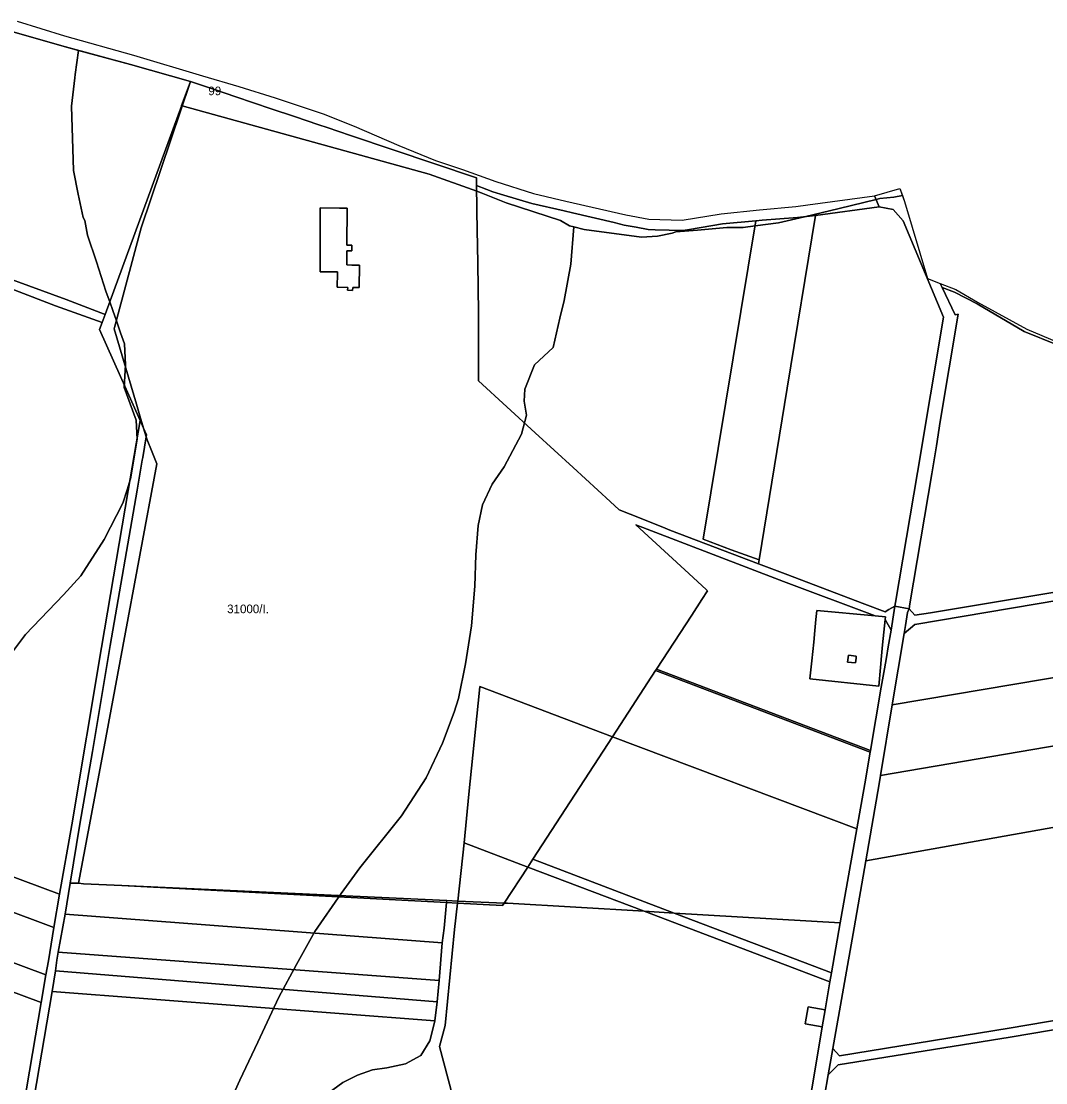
# Model space of a CAD drawing. Extents: x -541351 to -537540, y -1162694 to -1159725.
# Drawn here: x -540379 to -539786, y -1160416 to -1159801 of the extents above; entities that cross this region are included whole.
import ezdxf

# ---------------------------------------------------------------- set-up
doc = ezdxf.new("R2010")
doc.units = 0
for name, color, linetype in [('95560013', 7, 'Continuous'), ('95610013', 7, 'Continuous'), ('95640013', 7, 'Continuous'), ('95660013', 7, 'Continuous')]:
    doc.layers.add(name, color=color, linetype=linetype)

msp = doc.modelspace()

# ---------------------------------------------------------------- linework, layer by layer
at = {"layer": '95560013'}
for points in [[(-540392.94, -1159808.75), (-540387.33, -1159805.56), (-540383.07, -1159807.44), (-540355.38, -1159815.32), (-540315.69, -1159826.05), (-540281.01, -1159835.88), (-540330.36, -1159970.74), (-540352.96, -1159962.05), (-540409.96, -1159941.32), (-540413.54, -1159934.22), (-540400.75, -1159856.93)], [(-540356.83, -1160306.42), (-540508.48, -1160249.81), (-540502.49, -1160230.24), (-540493.25, -1160200.09), (-540483.27, -1160166.95), (-540480.24, -1160158.64), (-540461.87, -1160101.94), (-540442.45, -1160037.81), (-540415.15, -1159950.06), (-540408.75, -1159946.72), (-540359.07, -1159965.85), (-540332.08, -1159975.44), (-540333.53, -1159979.4), (-540310.02, -1160032.13), (-540317.01, -1160072.74), (-540332.5, -1160163.53), (-540349.68, -1160266.25)], [(-539861.7, -1160150.32), (-539749.73, -1160131.42), (-539678.3, -1160119.6), (-539674.35, -1160123.79), (-539681.25, -1160164.2), (-539874.79, -1160196.79), (-539867.81, -1160155.49)], [(-539874.79, -1160196.79), (-539681.25, -1160164.2), (-539688.29, -1160204.74), (-539881.63, -1160237.63)], [(-539695.22, -1160244.7), (-539696.27, -1160252.43), (-539890.14, -1160287.05), (-539882.34, -1160242.43), (-539881.63, -1160237.63), (-539688.29, -1160204.74)], [(-539905.29, -1160399.99), (-539909.12, -1160395.76), (-539896.76, -1160325.74), (-539890.14, -1160287.05), (-539696.27, -1160252.43), (-539714.91, -1160363.54), (-539720.67, -1160369.29), (-539807.19, -1160383.95)], [(-540514.38, -1160267.98), (-540360.1, -1160325.54), (-540363.17, -1160344.9), (-540364.58, -1160352.98), (-540522.49, -1160294.25)], [(-540522.49, -1160294.25), (-540364.58, -1160352.98), (-540367.38, -1160369.03), (-540527.1, -1160309.52)], [(-540134.18, -1160326.07), (-540135.3, -1160334.47), (-540353.51, -1160317.83), (-540350.6, -1160299.99), (-540345.66, -1160300.06), (-540342.83, -1160300.35), (-540320.73, -1160301.36), (-540132.7, -1160311.22)], [(-540132.7, -1160311.22), (-540320.73, -1160301.36), (-540132.58, -1160310.01)], [(-540527.1, -1160309.52), (-540367.38, -1160369.03), (-540379.07, -1160438.35), (-540385.21, -1160475.93), (-540388.61, -1160496.72), (-540565.8, -1160430.3), (-540549.55, -1160378.18), (-540535.84, -1160336.23)], [(-540126.4, -1160311.55), (-540132.7, -1160311.22), (-540132.58, -1160310.01), (-540126.26, -1160310.3)], [(-539919.82, -1160409.86), (-539934.65, -1160497.18), (-539939.3, -1160504.82), (-539943.59, -1160508.57), (-539953.62, -1160517.32), (-540120.93, -1160454.7), (-540124.57, -1160440.83), (-540129.29, -1160422.87), (-540136.74, -1160394.52), (-540133.58, -1160382.33), (-540128.1, -1160326.8), (-540126.4, -1160311.55), (-540100.25, -1160312.92), (-540099.35, -1160311.53), (-540097.45, -1160311.62), (-540018.39, -1160316.26), (-539910.82, -1160357.17), (-539913.57, -1160373.29), (-539923.43, -1160371.6), (-539925.11, -1160381.46), (-539915.26, -1160383.15)], [(-540126.4, -1160311.55), (-540126.26, -1160310.3), (-540099.35, -1160311.53), (-540100.25, -1160312.92)], [(-539910.82, -1160357.17), (-540018.39, -1160316.26), (-540001.04, -1160317.28), (-539909.92, -1160351.93)], [(-540353.51, -1160317.83), (-540135.3, -1160334.47), (-540137.05, -1160356.31), (-540357.49, -1160339.82)], [(-539909.92, -1160351.93), (-540001.04, -1160317.28), (-539904.97, -1160322.91)], [(-540358.21, -1160344.57), (-540357.49, -1160339.82), (-540137.05, -1160356.31), (-540138.11, -1160368.57), (-540359.02, -1160350.72)], [(-540139.42, -1160379.64), (-540361.01, -1160362.65), (-540359.02, -1160350.72), (-540138.11, -1160368.57)], [(-539622.59, -1160379.21), (-539631.8, -1160405.4), (-539638.38, -1160424.12), (-539641.15, -1160432), (-539644.34, -1160446.97), (-539647.54, -1160461.93), (-539784.61, -1160485.12), (-539921.72, -1160508.25), (-539926.62, -1160497.29), (-539911.84, -1160410.99), (-539905.99, -1160405.21), (-539806.59, -1160389.16), (-539702.88, -1160371.48), (-539612.64, -1160356.38), (-539617.44, -1160367.38)], [(-540192.75, -1160415.42), (-540201.36, -1160421.81), (-540204.8, -1160432.12), (-540205.99, -1160438.05), (-540371.68, -1160425.08), (-540361.01, -1160362.65), (-540139.42, -1160379.64), (-540139.64, -1160380.67), (-540142.35, -1160391.33), (-540147.64, -1160399.81), (-540156.43, -1160404.54), (-540167.21, -1160406.8), (-540175.62, -1160408.05), (-540184.29, -1160411.12)], [(-539913.57, -1160373.29), (-539915.26, -1160383.15), (-539925.11, -1160381.46), (-539923.43, -1160371.6)]]:
    msp.add_lwpolyline(points, close=True, dxfattribs=at)
for points in [[(-540201.36, -1160421.81), (-540192.75, -1160415.42), (-540184.29, -1160411.12), (-540175.62, -1160408.05), (-540167.21, -1160406.8), (-540156.43, -1160404.54), (-540147.64, -1160399.81), (-540142.35, -1160391.33), (-540139.64, -1160380.67), (-540139.42, -1160379.64), (-540138.11, -1160368.57), (-540137.05, -1160356.31), (-540135.3, -1160334.47), (-540134.18, -1160326.07), (-540132.7, -1160311.22), (-540126.4, -1160311.55), (-540128.1, -1160326.8), (-540133.58, -1160382.33), (-540136.74, -1160394.52), (-540129.29, -1160422.87)], [(-539702.88, -1160371.48), (-539806.59, -1160389.16), (-539905.99, -1160405.21), (-539911.84, -1160410.99), (-539909.12, -1160395.76), (-539905.29, -1160399.99), (-539807.19, -1160383.95), (-539720.67, -1160369.29)]]:
    msp.add_lwpolyline(points, dxfattribs=at)
at = {"layer": '95610013'}
msp.add_lwpolyline([(-540356.83, -1160306.42), (-540360.1, -1160325.54), (-540514.38, -1160267.98), (-540512.69, -1160262.74), (-540508.48, -1160249.81)], close=True, dxfattribs=at)
at = {"layer": '95640013'}
for points in [[(-540381.17, -1159801.03), (-540353.86, -1159809.47), (-540313.98, -1159820.68), (-540273.9, -1159832.58), (-540253.02, -1159838.81), (-540231.99, -1159845.43), (-540204.14, -1159854.61), (-540186.16, -1159861.7), (-540160.34, -1159872.99), (-540139.14, -1159881.68), (-540123.57, -1159886.83), (-540104.23, -1159893.79), (-540082.45, -1159900.78), (-540063.64, -1159905.2), (-540028.95, -1159913.17), (-540015.69, -1159915.65), (-539996.27, -1159916.14), (-539973.83, -1159912.54), (-539951.52, -1159910.12), (-539930.48, -1159908.19), (-539923.64, -1159907.28), (-539884.96, -1159902.13), (-539882.33, -1159908.49), (-539919.19, -1159913.5), (-539929.66, -1159914.61), (-539950.01, -1159916.19), (-539953.64, -1159916.52), (-539973.07, -1159918.29), (-539992.07, -1159921.5), (-539995.75, -1159922.12), (-540012.02, -1159921.72), (-540016.01, -1159921.62), (-540023.04, -1159920.31), (-540029.9, -1159919.03), (-540035.79, -1159917.63), (-540059.89, -1159911.91), (-540064.68, -1159910.77), (-540083.33, -1159906.57), (-540099.65, -1159901.66), (-540105.86, -1159899.79), (-540109.43, -1159898.41), (-540115.3, -1159896.16), (-540115.35, -1159891.67), (-540188.28, -1159867.11), (-540201.81, -1159862.55), (-540206.56, -1159860.95), (-540220.81, -1159856.16), (-540234.15, -1159851.66), (-540254.76, -1159844.72), (-540267.64, -1159840.39), (-540281.01, -1159835.88), (-540315.69, -1159826.05), (-540355.38, -1159815.32), (-540383.07, -1159807.44)], [(-539779.23, -1159988.26), (-539798.34, -1159980.7), (-539825.68, -1159964.64), (-539838.77, -1159957.82), (-539845.93, -1159955.11), (-539847.07, -1159952.76), (-539837.92, -1159956.31), (-539825.4, -1159963.61), (-539796.96, -1159979.23), (-539779.53, -1159986.52)], [(-539750.65, -1160126.47), (-539852.54, -1160143.49), (-539861.77, -1160144.89), (-539864.98, -1160141.1), (-539864.5, -1160138.25), (-539851.79, -1160063.11), (-539849.21, -1160046.91), (-539846.96, -1160032.69), (-539836.67, -1159970.59), (-539838.29, -1159970.9), (-539845.93, -1159955.11), (-539838.77, -1159957.82), (-539825.68, -1159964.64), (-539798.34, -1159980.7), (-539779.23, -1159988.26)], [(-540379.07, -1160438.35), (-540367.38, -1160369.03), (-540364.58, -1160352.98), (-540363.17, -1160344.9), (-540360.1, -1160325.54), (-540356.83, -1160306.42), (-540349.68, -1160266.25), (-540332.5, -1160163.53), (-540317.01, -1160072.74), (-540310.02, -1160032.13), (-540308.05, -1160036.54), (-540306.51, -1160041.57), (-540308.57, -1160053.59), (-540308.83, -1160055.13), (-540311.8, -1160072.45), (-540327.33, -1160162.37), (-540337.62, -1160223.7), (-540345.01, -1160265.76), (-540350.6, -1160299.99), (-540353.51, -1160317.83), (-540357.49, -1160339.82), (-540358.21, -1160344.57), (-540359.02, -1160350.72), (-540361.01, -1160362.65), (-540371.68, -1160425.08)], [(-539934.65, -1160497.18), (-539919.82, -1160409.86), (-539915.26, -1160383.15), (-539913.57, -1160373.29), (-539910.82, -1160357.17), (-539909.92, -1160351.93), (-539904.97, -1160322.91), (-539895.33, -1160268.57), (-539890.69, -1160242.45), (-539887.57, -1160224.18), (-539887.4, -1160223.2), (-539881.12, -1160186.5), (-539879.32, -1160175.96), (-539878.19, -1160169.34), (-539877.14, -1160163.23), (-539875.48, -1160153.53), (-539873.62, -1160142.07), (-539873.21, -1160139.53), (-539864.98, -1160141.1), (-539865.94, -1160143.31), (-539867.03, -1160150.82), (-539867.81, -1160155.49), (-539874.79, -1160196.79), (-539881.63, -1160237.63), (-539882.34, -1160242.43), (-539890.14, -1160287.05), (-539896.76, -1160325.74), (-539909.12, -1160395.76), (-539911.84, -1160410.99), (-539926.62, -1160497.29)]]:
    msp.add_lwpolyline(points, dxfattribs=at)
for points in [[(-540114.15, -1160009.28), (-540081.35, -1160039.35), (-540059.54, -1160059.34), (-540037.99, -1160079.08), (-540032.85, -1160083.79), (-540020.15, -1160088.95), (-540006.2, -1160094.54), (-540003.47, -1160095.63), (-539952.14, -1160115.13), (-539936.7, -1160120.97), (-539890.67, -1160138.4), (-539878.88, -1160142.86), (-539876.7, -1160141.6), (-539873.21, -1160139.53), (-539873.62, -1160142.07), (-539875.48, -1160153.53), (-539878.93, -1160147.41), (-539878.77, -1160145.8), (-539884.65, -1160145.26), (-539937.62, -1160125.33), (-540016.67, -1160095.1), (-540023.21, -1160092.63), (-539994.82, -1160118.65), (-539982.55, -1160129.89), (-539981.66, -1160130.71), (-539985, -1160135.84), (-539990.85, -1160144.83), (-540011.18, -1160176.06), (-540011.71, -1160176.88), (-540036.63, -1160215.17), (-540113.4, -1160186.16), (-540113.61, -1160188.22), (-540119.79, -1160248.54), (-540122.5, -1160276.66), (-540126.26, -1160310.3), (-540132.58, -1160310.01), (-540320.73, -1160301.36), (-540342.83, -1160300.35), (-540345.66, -1160300.06), (-540331.53, -1160224.16), (-540320.13, -1160162.91), (-540300.46, -1160057.21), (-540303.55, -1160049.43), (-540305.99, -1160043.28), (-540306.51, -1160041.57), (-540306.32, -1160040.43), (-540308.05, -1160036.54), (-540309.61, -1160031.46), (-540309.79, -1160030.84), (-540312.2, -1160022.66), (-540325.05, -1159979.1), (-540324.82, -1159978.24), (-540323.53, -1159973.38), (-540309.48, -1159920.55), (-540281.01, -1159835.88), (-540267.64, -1159840.39), (-540254.76, -1159844.72), (-540234.15, -1159851.66), (-540220.81, -1159856.16), (-540206.56, -1159860.95), (-540201.81, -1159862.55), (-540188.28, -1159867.11), (-540115.35, -1159891.67), (-540115.3, -1159896.16), (-540115, -1159923.02), (-540114.86, -1159930.13), (-540114.36, -1159954.32), (-540114.34, -1159959.41), (-540114.32, -1159965.74), (-540114.23, -1159988.02)], [(-540308.05, -1160036.54), (-540310.02, -1160032.13), (-540333.53, -1159979.4), (-540332.08, -1159975.44), (-540330.36, -1159970.74), (-540281.01, -1159835.88), (-540309.48, -1159920.55), (-540323.53, -1159973.38), (-540324.82, -1159978.24), (-540325.05, -1159979.1), (-540312.2, -1160022.66), (-540309.79, -1160030.84), (-540309.61, -1160031.46)], [(-539973.07, -1159918.29), (-539953.64, -1159916.52), (-539984.21, -1160100.77), (-539967.97, -1160107.08), (-539951.75, -1160112.76), (-539952.14, -1160115.13), (-540003.47, -1160095.63), (-540006.2, -1160094.54), (-540020.15, -1160088.95), (-540032.85, -1160083.79), (-540037.99, -1160079.08), (-540059.54, -1160059.34), (-540081.35, -1160039.35), (-540114.15, -1160009.28), (-540114.23, -1159988.02), (-540114.32, -1159965.74), (-540114.34, -1159959.41), (-540114.36, -1159954.32), (-540114.86, -1159930.13), (-540115, -1159923.02), (-540115.3, -1159896.16), (-540109.43, -1159898.41), (-540105.86, -1159899.79), (-540099.65, -1159901.66), (-540083.33, -1159906.57), (-540064.68, -1159910.77), (-540059.89, -1159911.91), (-540035.79, -1159917.63), (-540029.9, -1159919.03), (-540023.04, -1159920.31), (-540016.01, -1159921.62), (-540012.02, -1159921.72), (-539995.75, -1159922.12), (-539992.07, -1159921.5)], [(-539845.07, -1159972.24), (-539868.5, -1159916.51), (-539874.18, -1159909.94), (-539882.33, -1159908.49), (-539884.96, -1159902.13), (-539870.3, -1159897.92), (-539867.6, -1159905.3), (-539854.42, -1159949.89), (-539847.07, -1159952.76), (-539845.93, -1159955.11), (-539838.29, -1159970.9), (-539836.67, -1159970.59), (-539846.96, -1160032.69), (-539849.21, -1160046.91), (-539851.79, -1160063.11), (-539864.5, -1160138.25), (-539864.98, -1160141.1), (-539873.21, -1160139.53), (-539872.87, -1160137.5), (-539860.16, -1160062.17)], [(-540422.33, -1159937.95), (-540409.96, -1159941.32), (-540352.96, -1159962.05), (-540330.36, -1159970.74), (-540332.08, -1159975.44), (-540359.07, -1159965.85), (-540408.75, -1159946.72), (-540418.31, -1159943.64), (-540423.17, -1159943.05), (-540480.83, -1159935.64), (-540563.34, -1159924.9), (-540668.76, -1159911.89), (-540668.5, -1159907.14), (-540664.02, -1159907.64), (-540618.99, -1159912.95), (-540586.55, -1159916.94), (-540562.46, -1159920.09), (-540558.18, -1159920.55), (-540543.65, -1159922.47), (-540481.31, -1159930.52)], [(-540195.98, -1159954.98), (-540195.88, -1159946.8), (-540195.87, -1159946.05), (-540205.93, -1159946.12), (-540205.8, -1159908.96), (-540194.76, -1159909.17), (-540192.05, -1159909.23), (-540190.25, -1159909.26), (-540190.42, -1159930.65), (-540187.5, -1159930.68), (-540187.52, -1159933.91), (-540190.45, -1159933.89), (-540190.53, -1159942.12), (-540187.63, -1159942.15), (-540183.02, -1159942.2), (-540183.24, -1159955.16), (-540187.05, -1159955.11), (-540187.07, -1159956.81), (-540189.97, -1159956.77), (-540189.95, -1159955.07), (-540195.53, -1159954.99)], [(-540189.97, -1159956.77), (-540187.07, -1159956.81), (-540187.05, -1159955.11), (-540183.24, -1159955.16), (-540183.02, -1159942.2), (-540187.63, -1159942.15), (-540190.53, -1159942.12), (-540190.45, -1159933.89), (-540187.52, -1159933.91), (-540187.5, -1159930.68), (-540190.42, -1159930.65), (-540190.25, -1159909.26), (-540192.05, -1159909.23), (-540194.76, -1159909.17), (-540205.8, -1159908.96), (-540205.93, -1159946.12), (-540195.87, -1159946.05), (-540195.88, -1159946.8), (-540195.98, -1159954.98), (-540195.53, -1159954.99), (-540189.95, -1159955.07)], [(-539876.7, -1160141.6), (-539878.88, -1160142.86), (-539890.67, -1160138.4), (-539936.7, -1160120.97), (-539952.14, -1160115.13), (-539951.75, -1160112.76), (-539935.57, -1160013.47), (-539919.19, -1159913.5), (-539882.33, -1159908.49), (-539874.18, -1159909.94), (-539868.5, -1159916.51), (-539845.07, -1159972.24), (-539860.16, -1160062.17), (-539872.87, -1160137.5), (-539873.21, -1160139.53)], [(-539950.01, -1159916.19), (-539929.66, -1159914.61), (-539919.19, -1159913.5), (-539935.57, -1160013.47), (-539951.75, -1160112.76), (-539967.97, -1160107.08), (-539984.21, -1160100.77), (-539953.64, -1159916.52)], [(-540308.05, -1160036.54), (-540306.32, -1160040.43), (-540306.51, -1160041.57)], [(-540345.66, -1160300.06), (-540350.6, -1160299.99), (-540345.01, -1160265.76), (-540337.62, -1160223.7), (-540327.33, -1160162.37), (-540311.8, -1160072.45), (-540308.83, -1160055.13), (-540308.57, -1160053.59), (-540306.51, -1160041.57), (-540305.99, -1160043.28), (-540303.55, -1160049.43), (-540300.46, -1160057.21), (-540320.13, -1160162.91), (-540331.53, -1160224.16)], [(-539884.65, -1160145.26), (-539918.38, -1160142.14), (-539918.92, -1160147.4), (-539919.56, -1160153.7), (-539920.25, -1160160.44), (-539921.36, -1160171.22), (-539922.43, -1160181.71), (-539882.63, -1160185.93), (-539881.59, -1160175.1), (-539880.94, -1160168.3), (-539880.33, -1160162.02), (-539878.93, -1160147.41), (-539875.48, -1160153.53), (-539877.14, -1160163.23), (-539878.19, -1160169.34), (-539879.32, -1160175.96), (-539881.12, -1160186.5), (-539887.4, -1160223.2), (-540011.18, -1160176.06), (-539990.85, -1160144.83), (-539985, -1160135.84), (-539981.66, -1160130.71), (-539982.55, -1160129.89), (-539994.82, -1160118.65), (-540023.21, -1160092.63), (-540016.67, -1160095.1), (-539937.62, -1160125.33)], [(-539864.98, -1160141.1), (-539861.77, -1160144.89), (-539852.54, -1160143.49), (-539750.65, -1160126.47), (-539709.27, -1160119.9), (-539696.46, -1160117.7), (-539613.04, -1160103.64), (-539532.31, -1160089.25), (-539531.13, -1160089.89), (-539533.26, -1160094.63), (-539534.95, -1160094.86), (-539566.81, -1160100.08), (-539577.54, -1160102), (-539612.07, -1160108.19), (-539618.67, -1160109.28), (-539664, -1160116.8), (-539669.5, -1160118.03), (-539678.3, -1160119.6), (-539749.73, -1160131.42), (-539861.7, -1160150.32), (-539867.81, -1160155.49), (-539867.03, -1160150.82), (-539865.94, -1160143.31)], [(-539920.25, -1160160.44), (-539919.56, -1160153.7), (-539918.92, -1160147.4), (-539918.38, -1160142.14), (-539884.65, -1160145.26), (-539878.77, -1160145.8), (-539878.93, -1160147.41), (-539880.33, -1160162.02), (-539880.94, -1160168.3), (-539881.59, -1160175.1), (-539882.63, -1160185.93), (-539922.43, -1160181.71), (-539921.36, -1160171.22)], [(-539895.98, -1160172.44), (-539895.69, -1160169.76), (-539895.56, -1160168.54), (-539900.14, -1160168.08), (-539900.58, -1160172.01)], [(-539895.69, -1160169.76), (-539895.98, -1160172.44), (-539900.58, -1160172.01), (-539900.14, -1160168.08), (-539895.56, -1160168.54)], [(-539895.33, -1160268.57), (-540036.63, -1160215.17), (-540011.71, -1160176.88), (-539887.57, -1160224.18), (-539890.69, -1160242.45)], [(-539887.4, -1160223.2), (-539887.57, -1160224.18), (-540011.71, -1160176.88), (-540011.18, -1160176.06)], [(-540085.75, -1160290.64), (-540122.5, -1160276.66), (-540119.79, -1160248.54), (-540113.61, -1160188.22), (-540113.4, -1160186.16), (-540036.63, -1160215.17), (-540082.84, -1160286.17)], [(-539895.33, -1160268.57), (-539904.97, -1160322.91), (-540001.04, -1160317.28), (-540082.84, -1160286.17), (-540036.63, -1160215.17)], [(-540085.75, -1160290.64), (-540099.35, -1160311.53), (-540126.26, -1160310.3), (-540122.5, -1160276.66)], [(-540099.35, -1160311.53), (-540085.75, -1160290.64), (-540018.39, -1160316.26), (-540097.45, -1160311.62)], [(-540085.75, -1160290.64), (-540082.84, -1160286.17), (-540001.04, -1160317.28), (-540018.39, -1160316.26)]]:
    msp.add_lwpolyline(points, close=True, dxfattribs=at)
at = {"layer": '95660013'}
for points in [[(-540381.17, -1159801.03), (-540353.86, -1159809.47), (-540313.98, -1159820.68), (-540273.9, -1159832.58), (-540253.02, -1159838.81), (-540231.99, -1159845.43), (-540204.14, -1159854.61), (-540186.16, -1159861.7), (-540160.34, -1159872.99), (-540139.14, -1159881.68), (-540123.57, -1159886.83), (-540104.23, -1159893.79), (-540082.45, -1159900.78), (-540063.64, -1159905.2), (-540028.95, -1159913.17), (-540015.69, -1159915.65), (-539996.27, -1159916.14), (-539973.83, -1159912.54), (-539951.52, -1159910.12), (-539930.48, -1159908.19), (-539923.64, -1159907.28), (-539884.96, -1159902.13), (-539870.3, -1159897.92), (-539868.82, -1159901.97), (-539873.84, -1159902.89), (-539881.93, -1159903.74), (-539884.08, -1159904.25), (-539905.46, -1159909.37), (-539925.57, -1159914.18), (-539940.67, -1159917.79), (-539954.13, -1159919.47), (-539961.1, -1159920.34), (-539970.47, -1159920.34), (-539987.5, -1159922.04), (-539999.94, -1159922.9), (-540000, -1159922.92), (-540002.07, -1159923.7), (-540010.57, -1159925.38), (-540019.92, -1159926.1), (-540053.08, -1159921.6), (-540059.04, -1159920.07), (-540061.59, -1159919.41), (-540066.69, -1159916.43), (-540098.15, -1159906.23), (-540112.6, -1159900.28), (-540115.26, -1159899.34), (-540142.78, -1159889.65), (-540285.74, -1159849.94), (-540285.81, -1159849.92), (-540286.12, -1159849.83), (-540281.01, -1159835.88), (-540315.69, -1159826.05), (-540345.81, -1159817.91), (-540355.38, -1159815.32), (-540383.07, -1159807.44)], [(-540383.07, -1159807.44), (-540355.38, -1159815.32), (-540345.81, -1159817.91), (-540347.69, -1159831.83), (-540347.92, -1159833.79), (-540349.82, -1159850.11), (-540348.54, -1159887.52), (-540345.99, -1159901.13), (-540343.01, -1159914.73), (-540342.16, -1159916.43), (-540340.46, -1159924.93), (-540335.36, -1159940.24), (-540329.83, -1159957.24), (-540328.53, -1159961.01), (-540327.69, -1159963.43), (-540325.94, -1159968.47), (-540323.83, -1159974.52), (-540321.41, -1159981.49), (-540319.21, -1159987.85), (-540318.62, -1160000), (-540319.31, -1160013), (-540312.37, -1160032), (-540311.81, -1160043), (-540315.69, -1160066), (-540317.66, -1160072.22), (-540320.12, -1160080), (-540330.81, -1160101), (-540344.31, -1160122), (-540354.5, -1160133), (-540376.5, -1160156), (-540386.87, -1160170)], [(-540386.87, -1160170), (-540376.5, -1160156), (-540354.5, -1160133), (-540344.31, -1160122), (-540330.81, -1160101), (-540320.12, -1160080), (-540317.66, -1160072.22), (-540315.69, -1160066), (-540311.81, -1160043), (-540312.37, -1160032), (-540319.31, -1160013), (-540318.62, -1160000), (-540319.21, -1159987.85), (-540321.41, -1159981.49), (-540323.83, -1159974.52), (-540325.94, -1159968.47), (-540327.69, -1159963.43), (-540328.53, -1159961.01), (-540329.83, -1159957.24), (-540335.36, -1159940.24), (-540340.46, -1159924.93), (-540342.16, -1159916.43), (-540343.01, -1159914.73), (-540345.99, -1159901.13), (-540348.54, -1159887.52), (-540349.82, -1159850.11), (-540347.92, -1159833.79), (-540347.69, -1159831.83), (-540345.81, -1159817.91), (-540315.69, -1159826.05), (-540281.01, -1159835.88), (-540286.12, -1159849.83), (-540285.81, -1159849.92), (-540285.74, -1159849.94), (-540142.78, -1159889.65), (-540115.26, -1159899.34), (-540112.6, -1159900.28), (-540098.15, -1159906.23), (-540066.69, -1159916.43), (-540061.59, -1159919.41), (-540059.04, -1159920.07), (-540060.74, -1159941.65), (-540064.56, -1159962.77), (-540067.11, -1159972.97), (-540070.94, -1159989.98), (-540081.78, -1160000), (-540087.37, -1160014), (-540087.87, -1160021), (-540086.37, -1160029), (-540089.37, -1160040), (-540099.37, -1160059), (-540106.37, -1160069), (-540111.87, -1160081), (-540114.37, -1160093), (-540115.81, -1160110), (-540116.31, -1160128), (-540118.31, -1160151), (-540121.81, -1160173), (-540125.81, -1160193), (-540128.31, -1160201), (-540135, -1160219), (-540144.5, -1160239), (-540158.87, -1160261), (-540182.87, -1160291), (-540193.81, -1160306), (-540209, -1160328), (-540219.5, -1160347), (-540229.87, -1160366), (-540241.87, -1160392), (-540252.37, -1160414), (-540264.12, -1160440)], [(-540264.12, -1160440), (-540252.37, -1160414), (-540241.87, -1160392), (-540229.87, -1160366), (-540219.5, -1160347), (-540209, -1160328), (-540193.81, -1160306), (-540182.87, -1160291), (-540158.87, -1160261), (-540144.5, -1160239), (-540135, -1160219), (-540128.31, -1160201), (-540125.81, -1160193), (-540121.81, -1160173), (-540118.31, -1160151), (-540116.31, -1160128), (-540115.81, -1160110), (-540114.37, -1160093), (-540111.87, -1160081), (-540106.37, -1160069), (-540099.37, -1160059), (-540089.37, -1160040), (-540086.37, -1160029), (-540087.87, -1160021), (-540087.37, -1160014), (-540081.78, -1160000), (-540070.94, -1159989.98), (-540067.11, -1159972.97), (-540064.56, -1159962.77), (-540060.74, -1159941.65), (-540059.04, -1159920.07), (-540053.08, -1159921.6), (-540019.92, -1159926.1), (-540010.57, -1159925.38), (-540002.07, -1159923.7), (-540000, -1159922.92), (-539999.94, -1159922.9), (-539987.5, -1159922.04), (-539970.47, -1159920.34), (-539961.1, -1159920.34), (-539954.13, -1159919.47), (-539940.67, -1159917.79), (-539925.57, -1159914.18), (-539905.46, -1159909.37), (-539884.08, -1159904.25), (-539881.93, -1159903.74), (-539873.84, -1159902.89), (-539868.82, -1159901.97), (-539867.6, -1159905.3), (-539854.42, -1159949.89), (-539847.07, -1159952.76), (-539837.92, -1159956.31), (-539825.4, -1159963.61), (-539796.96, -1159979.23), (-539779.53, -1159986.52)]]:
    msp.add_lwpolyline(points, dxfattribs=at)

# ---------------------------------------------------------------- texts
for s, rotation, p in [('99', 0, (-540270.6, -1159843.86)), ('31000/I.', 360, (-540259.71, -1160143.7))]:
    msp.add_text(s, height=5, rotation=rotation, dxfattribs=at).set_placement(p)

doc.saveas('drawing.dxf')
